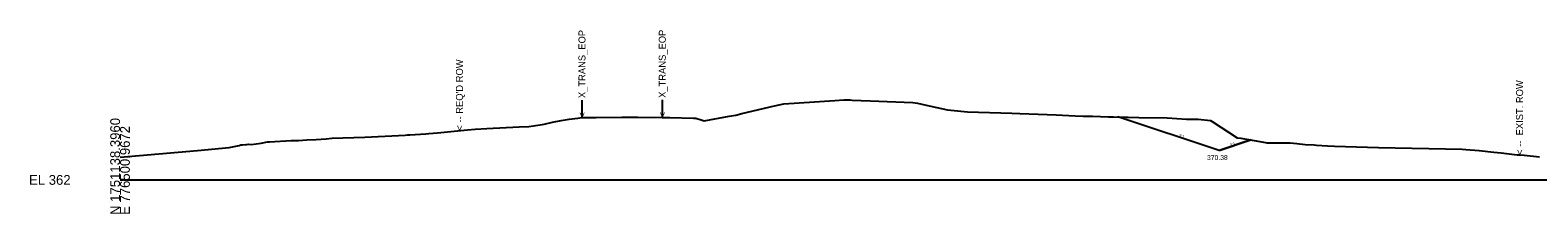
# Model space of a CAD drawing. Extents: x 776426 to 854588, y 1736205 to 1756790.
# Drawn here: x 805845.1 to 806276, y 1737705.1 to 1737757.5 of the extents above; entities that cross this region are included whole.
import ezdxf

# ---------------------------------------------------------------- set-up
doc = ezdxf.new("R2010")
doc.units = 0
for name, color, linetype in [('DTM CONTOURS_MAJOR_TX', 7, 'Continuous'), ('DTM_X_FLOW_ARROWS', 7, 'Continuous'), ('X_TRANS_EOP', 7, 'Continuous'), ('XS_M_SHAPES_EARTHWORK', 7, 'Continuous'), ('XS_P_FINISHED_GRADE', 7, 'Continuous'), ('XS_P_ROW', 7, 'Continuous'), ('XS_P_TX_DCH', 7, 'Continuous'), ('XS_P_TX_FS_BS', 7, 'Continuous'), ('XS_X_PAVEMENT', 7, 'Continuous'), ('XS_X_ROW', 7, 'Continuous')]:
    doc.layers.add(name, color=color, linetype=linetype)

msp = doc.modelspace()

# ---------------------------------------------------------------- linework, layer by layer
at = {"layer": 'DTM CONTOURS_MAJOR_TX'}
msp.add_line((805870.79, 1737714.76), (806370.79, 1737714.76), dxfattribs=at)
at = {"layer": 'DTM_X_FLOW_ARROWS'}
msp.add_lwpolyline([(805870.79, 1737721.23), (805892.96, 1737723.16), (805901.96, 1737724.04), (805904.8, 1737724.62), (805905.31, 1737724.78), (805905.8, 1737724.78), (805906.71, 1737724.89), (805907.04, 1737724.89), (805907.54, 1737724.92), (805908.27, 1737724.9), (805911.15, 1737725.26), (805912.91, 1737725.62), (805913.5, 1737725.62), (805919.71, 1737725.97), (805921.79, 1737726.06), (805924.21, 1737726.2), (805926.85, 1737726.32), (805929.68, 1737726.48), (805931.34, 1737726.67), (805940.76, 1737726.92), (805952.28, 1737727.56), (805952.97, 1737727.6), (805953.58, 1737727.6), (805956.67, 1737727.84), (805958.19, 1737727.95), (805959.03, 1737728.04), (805961.5, 1737728.24), (805970.1, 1737729.05), (805972.32, 1737729.21), (805975.6, 1737729.47), (805984.9, 1737729.96), (805987.62, 1737729.98), (805990.83, 1737730.46), (805991.97, 1737730.66), (805994.42, 1737731.26), (805996.9, 1737731.68), (805999.12, 1737732.14), (806001.64, 1737732.42), (806002.81, 1737732.55), (806006.85, 1737732.61), (806014.22, 1737732.69), (806018.74, 1737732.69), (806025.76, 1737732.62), (806027.92, 1737732.54), (806034.71, 1737732.38), (806035.32, 1737732.36), (806037.19, 1737731.82), (806037.73, 1737731.66), (806044.88, 1737733.01), (806046.75, 1737733.23), (806048.53, 1737733.77), (806057.81, 1737735.91), (806060.54, 1737736.52), (806064.88, 1737736.78), (806075.1, 1737737.47), (806077.65, 1737737.64), (806079.49, 1737737.61), (806080.05, 1737737.57), (806085.16, 1737737.34), (806097.35, 1737736.82), (806098.71, 1737736.63), (806101.18, 1737736.06), (806107.3, 1737734.78), (806112.99, 1737734.2), (806125.68, 1737733.8), (806127.99, 1737733.72), (806133.18, 1737733.58), (806138.32, 1737733.39), (806143.75, 1737733.03), (806146.1, 1737732.95), (806148.69, 1737732.93), (806153.25, 1737732.81), (806154.75, 1737732.82), (806161.96, 1737732.62), (806170.1, 1737732.47), (806175.58, 1737732.12), (806178.9, 1737732.07), (806182.46, 1737731.74), (806182.96, 1737731.42), (806190.05, 1737726.76), (806191.15, 1737726.68), (806198.21, 1737725.4), (806198.57, 1737725.37), (806201.94, 1737725.36), (806205.19, 1737725.34), (806207.17, 1737725.15), (806209.47, 1737724.85), (806212.12, 1737724.74), (806212.79, 1737724.64), (806215.88, 1737724.49), (806217.85, 1737724.37), (806230.46, 1737723.98), (806254.41, 1737723.57), (806255.47, 1737723.45), (806259.25, 1737723.15), (806263.43, 1737722.72), (806265.5, 1737722.48), (806270.1, 1737721.93), (806270.99, 1737721.89), (806272.06, 1737721.8), (806276.49, 1737721.32)], dxfattribs=at)
at = {"layer": 'X_TRANS_EOP'}
for p, q in [((806002.81, 1737737.55), (806002.81, 1737732.55)), ((806002.81, 1737737.55), (806002.81, 1737732.55)), ((806025.76, 1737737.62), (806025.76, 1737732.62)), ((806025.76, 1737737.62), (806025.76, 1737732.62))]:
    msp.add_line(p, q, dxfattribs=at)
at = {"layer": 'XS_M_SHAPES_EARTHWORK'}
msp.add_lwpolyline([(806184.95, 1737723.14), (806156.01, 1737732.79), (806161.96, 1737732.62), (806170.1, 1737732.47), (806175.58, 1737732.12), (806178.9, 1737732.07), (806182.46, 1737731.74), (806182.96, 1737731.42), (806190.05, 1737726.76), (806191.15, 1737726.68), (806194.02, 1737726.16)], close=True, dxfattribs=at)
at = {"layer": 'XS_P_FINISHED_GRADE'}
for q in [(806156.01, 1737732.79), (806194.02, 1737726.16)]:
    msp.add_line((806184.95, 1737723.14), q, dxfattribs=at)

# ---------------------------------------------------------------- texts
at = {"layer": 'DTM CONTOURS_MAJOR_TX'}
for s, p in [('N 1751138.3960', (805870.79, 1737704.76)), ('E 776500.9672', (805873.59, 1737704.76))]:
    msp.add_text(s, height=2.8, rotation=90, dxfattribs=at).set_placement(p)
msp.add_text('EL 362', height=2.8, dxfattribs=at).set_placement((805844.79, 1737713.36))
at = {"layer": 'XS_P_ROW'}
msp.add_text("< -- REQ'D ROW", height=2, rotation=90, dxfattribs=at).set_placement((805968.8, 1737728.83))
at = {"layer": 'XS_P_TX_DCH'}
msp.add_text('370.38', height=1.4, dxfattribs=at).set_placement((806181.46, 1737720.44))
at = {"layer": 'XS_P_TX_FS_BS'}
for rotation, p in [(341.5651, (806173.37, 1737727.2)), (18.4349, (806188.15, 1737724.36))]:
    msp.add_text('3:1', height=0.8, rotation=rotation, dxfattribs=at).set_placement(p)
at = {"layer": 'XS_X_PAVEMENT'}
for p in [(806003.81, 1737732.55), (806026.76, 1737732.62)]:
    msp.add_text('< --  X_TRANS_EOP', height=2, rotation=90, dxfattribs=at).set_placement(p)
at = {"layer": 'XS_X_ROW'}
msp.add_text('< --  EXIST. ROW', height=2, rotation=90, dxfattribs=at).set_placement((806271.79, 1737721.9))

doc.saveas('drawing.dxf')
